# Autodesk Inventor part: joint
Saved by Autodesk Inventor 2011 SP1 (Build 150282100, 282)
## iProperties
Created: 2010-12
Part Number: joint
Document SubType Name: Modeling
Designer: eric
Density: 1 g/cm^3
Author: eric
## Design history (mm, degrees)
feature "Base1"
node "Solide1"
node "Corps solides"
node "Corps surfaciques"
